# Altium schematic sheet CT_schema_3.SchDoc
size 293 x 156 mm
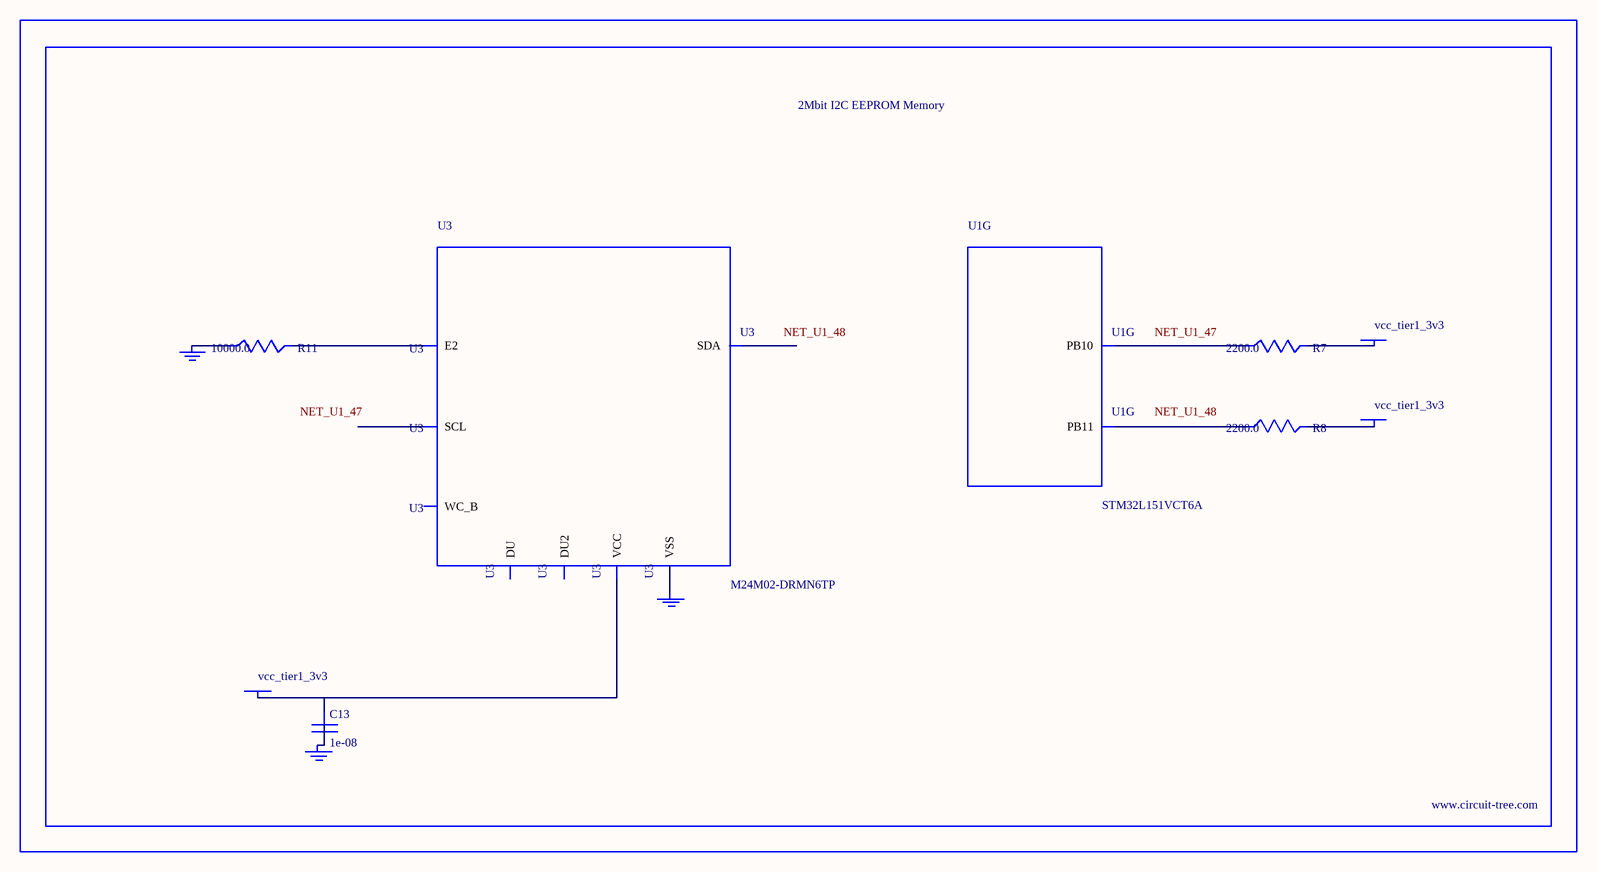
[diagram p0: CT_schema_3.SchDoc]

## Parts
BORDER2  (no value)
C13  1e-08  [C0402]
GND_INSTANCE_2_0  (no value)
GND_INSTANCE_2_1  (no value)
GND_INSTANCE_2_2  (no value)
POWER_INSTANCE_2_0  vcc_tier1_3v3
POWER_INSTANCE_2_1  vcc_tier1_3v3
POWER_INSTANCE_2_2  vcc_tier1_3v3
R7  2200.0  [R0603]
R8  2200.0  [R0603]
R11  10000.0  [R0603]
U1  STM32L151VCT6A  [LQFP100]  (part G of 10)
U3  M24M02-DRMN6TP  [SOIC-8]

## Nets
NetC13_1: C13.1 POWER_INSTANCE_2_0.0(PWR) U3.8(VCC)
NetC13_2: C13.2 GND_INSTANCE_2_1.0(GND)
NetGND_INSTANCE_2_0_0: GND_INSTANCE_2_0.0(GND) R11.1
NetGND_INSTANCE_2_2_0: GND_INSTANCE_2_2.0(GND) U3.4(VSS)
NetPOWER_INSTANCE_2_1_0: POWER_INSTANCE_2_1.0(PWR) R7.2
NetPOWER_INSTANCE_2_2_0: POWER_INSTANCE_2_2.0(PWR) R8.2
NetR7_1: R7.1 U1.47(PB10)
NetR8_1: R8.1 U1.48(PB11)
NetR11_2: R11.2 U3.3(E2)

Not connected (* = marked no-connect by the designer): U3 1(DU) 2(DU2) 5(SDA) 6(SCL) 7(WC_B)

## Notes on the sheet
- Labels drawn without touching a wire or pin: NET_U1_47, NET_U1_48

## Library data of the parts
BORDER2 = BORDER_PAGE2
C13 = C0402C103K3RAC
GND_INSTANCE_2_0-GND_INSTANCE_2_2 = GND
POWER_INSTANCE_2_0-POWER_INSTANCE_2_2 = PWR
R7 R8 = RC0603JR-072K2L
R11 = RC0603JR-0710KL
